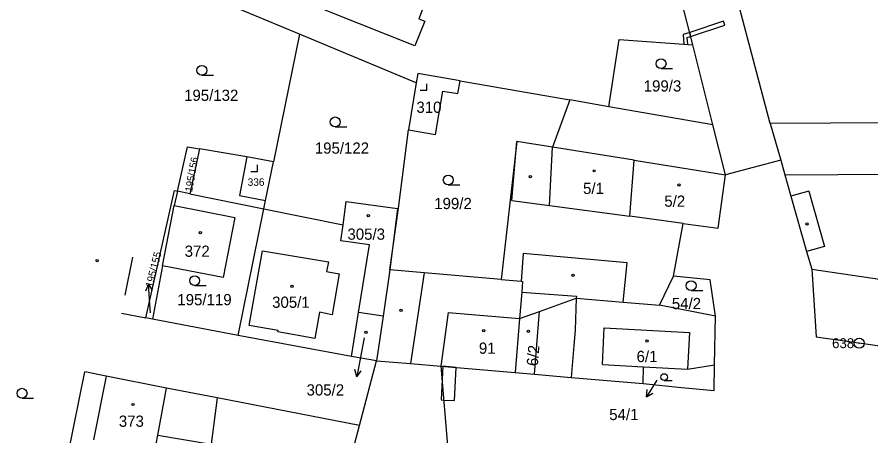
# Model space of a CAD drawing. Extents: x -783948 to -781889, y -1005870 to -1004430.
# Drawn here: x -782682.1 to -782552.8, y -1005413.9 to -1005350.5 of the extents above; entities that cross this region are included whole.
import ezdxf

# ---------------------------------------------------------------- set-up
doc = ezdxf.new("R2010")
doc.units = 0
for name, color, linetype in [('Vrstva 1', 7, 'Continuous'), ('Vrstva 13', 7, 'Continuous'), ('Vrstva 2', 7, 'Continuous'), ('Vrstva 3', 7, 'Continuous'), ('Vrstva 4', 7, 'Continuous'), ('Vrstva 5', 7, 'Continuous'), ('Vrstva 7', 7, 'Continuous'), ('Vrstva 8', 7, 'Continuous')]:
    doc.layers.add(name, color=color, linetype=linetype)

msp = doc.modelspace()

# ---------------------------------------------------------------- linework, layer by layer
at = {"layer": 'Vrstva 1'}
for p, q in [((-782568.05, -1005366.58), (-782581, -1005317.76)), ((-782639.31, -1005353.05), (-782666.74, -1005341.61)), ((-782579.79, -1005354.68), (-782581.54, -1005347.72)), ((-782639.31, -1005353.05), (-782643.26, -1005372.41)), ((-782621.64, -1005360.42), (-782639.31, -1005353.05)), ((-782576.74, -1005366.8), (-782579.79, -1005354.68)), ((-782621.64, -1005360.42), (-782622.85, -1005367.56)), ((-782614.99, -1005360.1), (-782598.41, -1005363.01)), ((-782598.41, -1005363.01), (-782601.05, -1005370.17)), ((-782592.52, -1005364.04), (-782598.41, -1005363.01)), ((-782576.74, -1005366.8), (-782592.52, -1005364.04)), ((-782518.53, -1005366.29), (-782568.05, -1005366.58)), ((-782574.83, -1005374.36), (-782576.74, -1005366.8)), ((-782568.05, -1005366.58), (-782566.48, -1005372.13)), ((-782654.49, -1005370.43), (-782655.91, -1005377.23)), ((-782566.48, -1005372.13), (-782574.83, -1005374.36)), ((-782662.57, -1005396.04), (-782658.25, -1005376.76)), ((-782658.25, -1005376.76), (-782657.8, -1005376.85)), ((-782657.8, -1005376.85), (-782658.29, -1005379.02)), ((-782655.91, -1005377.23), (-782657.8, -1005376.85)), ((-782655.91, -1005377.23), (-782644.71, -1005379.51)), ((-782660.09, -1005388.15), (-782658.29, -1005379.02)), ((-782632.73, -1005381.92), (-782632.25, -1005378.4)), ((-782632.25, -1005378.4), (-782624.5, -1005379.47)), ((-782648.63, -1005398.73), (-782644.71, -1005379.51)), ((-782644.71, -1005379.51), (-782632.73, -1005381.92)), ((-782624.5, -1005379.47), (-782625.63, -1005388.78)), ((-782633.07, -1005384.36), (-782632.73, -1005381.92)), ((-782582.71, -1005389.7), (-782581.23, -1005381.73)), ((-782660.09, -1005388.15), (-782661.6, -1005396.23)), ((-782625.63, -1005388.78), (-782626.66, -1005395.78)), ((-782584.84, -1005394.13), (-782582.71, -1005389.7)), ((-782576.37, -1005395.77), (-782584.84, -1005394.13)), ((-782666.25, -1005395.33), (-782662.57, -1005396.04)), ((-782661.6, -1005396.23), (-782662.57, -1005396.04)), ((-782631.45, -1005401.89), (-782630.38, -1005395.22)), ((-782626.66, -1005395.78), (-782630.38, -1005395.22)), ((-782626.66, -1005395.78), (-782627.67, -1005402.56)), ((-782606.01, -1005396.14), (-782606.67, -1005404.33)), ((-782576.48, -1005403.18), (-782576.37, -1005395.77)), ((-782648.63, -1005398.73), (-782661.6, -1005396.23)), ((-782631.45, -1005401.89), (-782648.63, -1005398.73)), ((-782627.67, -1005402.56), (-782631.45, -1005401.89)), ((-782630.22, -1005412.33), (-782627.67, -1005402.56)), ((-782617.91, -1005403.36), (-782616.88, -1005415.97)), ((-782617.91, -1005403.36), (-782606.67, -1005404.33)), ((-782674.64, -1005418.12), (-782671.83, -1005404.23)), ((-782668.6, -1005404.87), (-782671.83, -1005404.23)), ((-782668.6, -1005404.87), (-782670.5, -1005414.54)), ((-782598.18, -1005405.1), (-782587.31, -1005406.01)), ((-782587.31, -1005406.01), (-782581.49, -1005406.58)), ((-782651.78, -1005408.15), (-782652.71, -1005415.17)), ((-782630.22, -1005412.33), (-782651.78, -1005408.15)), ((-782637.85, -1005441.21), (-782630.22, -1005412.33))]:
    msp.add_line(p, q, dxfattribs=at)
for points in [[(-782635.77, -1005342.28), (-782632.66, -1005334.3), (-782632.25, -1005333.25), (-782630.42, -1005333.92), (-782615.9, -1005339.75), (-782612.83, -1005340.97), (-782613.21, -1005341.94), (-782615.78, -1005348.52), (-782619.8, -1005346.96), (-782621.28, -1005350.7), (-782620.33, -1005351.08), (-782621.85, -1005354.83), (-782634.45, -1005349.81), (-782638.09, -1005348.34), (-782635.77, -1005342.28)], [(-782592.52, -1005364.04), (-782590.91, -1005353.87), (-782579.79, -1005354.68)], [(-782614.99, -1005360.1), (-782621.4, -1005359), (-782621.64, -1005360.42)], [(-782622.85, -1005367.56), (-782618.76, -1005368.27), (-782617.61, -1005361.67), (-782615.34, -1005362.06), (-782614.99, -1005360.1)], [(-782625.63, -1005388.78), (-782624.32, -1005379.44), (-782622.85, -1005367.56)], [(-782657.8, -1005376.85), (-782656.28, -1005370.1), (-782654.49, -1005370.43)], [(-782601.05, -1005370.17), (-782606.45, -1005369.31), (-782608.79, -1005390.24)], [(-782581.23, -1005381.73), (-782589.31, -1005380.65), (-782588.65, -1005372.15), (-782601.05, -1005370.17)], [(-782643.26, -1005372.41), (-782647.3, -1005371.65), (-782654.49, -1005370.43)], [(-782644.71, -1005379.51), (-782644.45, -1005378.24), (-782643.26, -1005372.41)], [(-782566.48, -1005372.13), (-782565.86, -1005374.34), (-782564.92, -1005377.62), (-782562.55, -1005386), (-782561.79, -1005388.68), (-782561.13, -1005398.91), (-782523.94, -1005404.17), (-782523.08, -1005404.21)], [(-782581.23, -1005381.73), (-782575.93, -1005382.44), (-782574.83, -1005374.36)], [(-782658.29, -1005379.02), (-782649.14, -1005380.85), (-782650.89, -1005389.92), (-782660.09, -1005388.15)], [(-782630.38, -1005395.22), (-782628.75, -1005384.97), (-782633.07, -1005384.36)], [(-782608.79, -1005390.24), (-782620.45, -1005389.23), (-782625.63, -1005388.78)], [(-782608.79, -1005390.24), (-782605.78, -1005390.5), (-782605.56, -1005390.52), (-782605.69, -1005392.13), (-782606.01, -1005396.14)], [(-782576.37, -1005395.77), (-782577.18, -1005390.3), (-782582.71, -1005389.7)], [(-782606.01, -1005396.14), (-782603.01, -1005395.06), (-782597.43, -1005393.06)], [(-782597.43, -1005393.06), (-782597.6, -1005397.88), (-782597.79, -1005400.25), (-782598.18, -1005405.1)], [(-782597.43, -1005393.06), (-782590.35, -1005393.67), (-782584.84, -1005394.13)], [(-782627.67, -1005402.56), (-782622.5, -1005402.96), (-782617.91, -1005403.36)], [(-782587.31, -1005406.01), (-782587.25, -1005403.46), (-782580.59, -1005403.81), (-782576.48, -1005403.18)], [(-782581.49, -1005406.58), (-782576.57, -1005407.06), (-782576.48, -1005403.18)], [(-782651.78, -1005408.15), (-782659.44, -1005406.67), (-782668.6, -1005404.87)], [(-782606.67, -1005404.33), (-782603.77, -1005404.58), (-782598.18, -1005405.1)], [(-782661.28, -1005416.42), (-782660.79, -1005413.84), (-782652.71, -1005415.17)]]:
    msp.add_lwpolyline(points, dxfattribs=at)
at = {"layer": 'Vrstva 13'}
for points in [[(-782580.11, -1005353.4), (-782574.96, -1005351.67), (-782575.15, -1005351.1), (-782580.26, -1005352.82)], [(-782581.26, -1005353.1), (-782581.14, -1005354.58), (-782580.53, -1005354.63), (-782580.62, -1005353.54), (-782580.11, -1005353.4), (-782580.26, -1005352.82)], [(-782615.62, -1005403.56), (-782617.65, -1005403.38), (-782617.75, -1005405.36), (-782617.9, -1005408.47), (-782617.49, -1005408.49), (-782615.86, -1005408.57)]]:
    msp.add_lwpolyline(points, close=True, dxfattribs=at)
at = {"layer": 'Vrstva 3'}
for p, q in [((-782584.59, -1005358.27), (-782582.84, -1005358.27)), ((-782654.11, -1005359.28), (-782652.36, -1005359.28)), ((-782620.06, -1005361.55), (-782620.06, -1005360.55)), ((-782621.06, -1005361.55), (-782620.06, -1005361.55)), ((-782633.92, -1005367.1), (-782632.17, -1005367.1)), ((-782645.67, -1005373.84), (-782645.67, -1005372.84)), ((-782646.67, -1005373.84), (-782645.67, -1005373.84)), ((-782616.81, -1005375.9), (-782615.06, -1005375.9)), ((-782655.2, -1005391.15), (-782653.45, -1005391.15)), ((-782580.04, -1005391.91), (-782578.29, -1005391.91)), ((-782584.1, -1005405.51), (-782582.93, -1005405.51)), ((-782681.33, -1005408.22), (-782679.58, -1005408.22))]:
    msp.add_line(p, q, dxfattribs=at)
for centre, radius in [((-782584.59, -1005357.52), 0.75), ((-782654.11, -1005358.53), 0.75), ((-782633.92, -1005366.35), 0.75), ((-782616.81, -1005375.15), 0.75), ((-782655.2, -1005390.4), 0.75), ((-782580.04, -1005391.16), 0.75), ((-782584.11, -1005405.01), 0.502), ((-782681.33, -1005407.47), 0.75)]:
    msp.add_circle(centre, radius, dxfattribs=at)
at = {"layer": 'Vrstva 4'}
for p, q in [((-782607.16, -1005378.27), (-782606.45, -1005369.31)), ((-782601.5, -1005379.02), (-782601.05, -1005370.17)), ((-782647.3, -1005371.65), (-782648.43, -1005377.48)), ((-782588.65, -1005372.15), (-782574.83, -1005374.36)), ((-782565.86, -1005374.34), (-782518.77, -1005374.13)), ((-782648.43, -1005377.48), (-782644.45, -1005378.24)), ((-782562.24, -1005376.86), (-782564.92, -1005377.62)), ((-782562.24, -1005376.86), (-782559.85, -1005385.23)), ((-782607.16, -1005378.27), (-782601.5, -1005379.02)), ((-782601.5, -1005379.02), (-782589.31, -1005380.65)), ((-782559.85, -1005385.23), (-782562.55, -1005386)), ((-782665.71, -1005392.62), (-782664.55, -1005386.84)), ((-782645.73, -1005390.4), (-782644.95, -1005385.88)), ((-782644.95, -1005385.88), (-782634.95, -1005387.53)), ((-782605.46, -1005386.3), (-782605.78, -1005390.5)), ((-782589.7, -1005387.7), (-782605.46, -1005386.3)), ((-782634.95, -1005387.53), (-782635.22, -1005389.02)), ((-782590.35, -1005393.67), (-782589.7, -1005387.7)), ((-782635.22, -1005389.02), (-782633.3, -1005389.35)), ((-782633.3, -1005389.35), (-782634.37, -1005395.56)), ((-782620.45, -1005389.23), (-782622.5, -1005402.96)), ((-782561.79, -1005388.68), (-782541.32, -1005391.69)), ((-782646.97, -1005397.18), (-782645.73, -1005390.4)), ((-782605.69, -1005392.13), (-782597.41, -1005392.76)), ((-782597.41, -1005392.76), (-782597.43, -1005393.06)), ((-782636.3, -1005395.17), (-782637.03, -1005399.16)), ((-782634.37, -1005395.56), (-782636.3, -1005395.17)), ((-782616.83, -1005395.21), (-782617.91, -1005403.36)), ((-782616.83, -1005395.21), (-782606.01, -1005396.14)), ((-782603.77, -1005404.58), (-782603.06, -1005395.68)), ((-782603.06, -1005395.68), (-782603.01, -1005395.06)), ((-782642.57, -1005397.97), (-782646.97, -1005397.18)), ((-782642.61, -1005398.16), (-782642.57, -1005397.97)), ((-782637.03, -1005399.16), (-782642.61, -1005398.16)), ((-782593.48, -1005403.13), (-782587.25, -1005403.46)), ((-782660.79, -1005413.84), (-782659.44, -1005406.67))]:
    msp.add_line(p, q, dxfattribs=at)
msp.add_lwpolyline([(-782593.48, -1005403.13), (-782593.19, -1005397.57), (-782580.3, -1005398.25), (-782580.59, -1005403.81)], dxfattribs=at)
at = {"layer": 'Vrstva 5'}
for centre in [(-782594.72, -1005373.76), (-782604.39, -1005374.63), (-782581.88, -1005375.9), (-782628.92, -1005380.55), (-782562.52, -1005381.81), (-782654.34, -1005383.11), (-782669.96, -1005387.39), (-782597.91, -1005389.58), (-782640.44, -1005391.24), (-782623.95, -1005394.9), (-782629.24, -1005398.24), (-782611.44, -1005397.99), (-782604.68, -1005398.06), (-782586.7, -1005399.56), (-782664.52, -1005409.17)]:
    msp.add_circle(centre, 0.175, dxfattribs=at)
at = {"layer": 'Vrstva 7'}
for p, q in [((-782662.19, -1005390.95), (-782662.62, -1005391.98)), ((-782661.98, -1005393.94), (-782662.19, -1005390.95)), ((-782662.19, -1005390.95), (-782661.62, -1005391.91)), ((-782661.89, -1005395.27), (-782661.98, -1005393.94)), ((-782629.52, -1005399.05), (-782630.09, -1005402.01)), ((-782630.09, -1005402.01), (-782630.66, -1005404.96)), ((-782630.66, -1005404.96), (-782630.96, -1005403.88)), ((-782630.66, -1005404.96), (-782629.98, -1005404.07)), ((-782585.23, -1005405.46), (-782586.78, -1005408.03)), ((-782586.78, -1005408.03), (-782586.69, -1005406.92)), ((-782586.78, -1005408.03), (-782585.83, -1005407.43))]:
    msp.add_line(p, q, dxfattribs=at)
at = {"layer": 'Vrstva 8'}
for radius in [0.75, 0.03]:
    msp.add_circle((-782554.6, -1005399.88), radius, dxfattribs=at)

# ---------------------------------------------------------------- texts
at = {"layer": 'Vrstva 2'}
for s, height, p in [('199/3', 1.7, (-782587.22, -1005361.74)), ('195/132', 1.7, (-782656.8, -1005363.16)), ('310', 1.7, (-782621.63, -1005364.97)), ('195/122', 1.7, (-782637.01, -1005371.16)), ('336', 1.14, (-782647.17, -1005376.03)), ('5/1', 1.7, (-782596.4, -1005377.27)), ('199/2', 1.7, (-782618.93, -1005379.56)), ('5/2', 1.7, (-782584.1, -1005379.2)), ('305/3', 1.7, (-782632.07, -1005384.2)), ('372', 1.7, (-782656.71, -1005386.79)), ('195/119', 1.7, (-782657.82, -1005394.13)), ('305/1', 1.7, (-782643.47, -1005394.52)), ('54/2', 1.7, (-782582.96, -1005394.72)), ('91', 1.7, (-782612.17, -1005401.48)), ('6/1', 1.7, (-782588.3, -1005402.74)), ('305/2', 1.7, (-782638.26, -1005407.81)), ('54/1', 1.7, (-782592.44, -1005411.53)), ('373', 1.7, (-782666.68, -1005412.55))]:
    msp.add_text(s, height=height, dxfattribs=at).set_placement(p)
for s, height, rotation, p in [('195/156', 1.1, 80, (-782655.59, -1005377.02)), ('195/155', 1.139, 76, (-782661.55, -1005391.52)), ('6/2', 1.7, 85, (-782603.26, -1005403.4))]:
    msp.add_text(s, height=height, rotation=rotation, dxfattribs=at).set_placement(p)
at = {"layer": 'Vrstva 8'}
msp.add_text('638', height=1.5, dxfattribs=at).set_placement((-782558.7, -1005400.63))

doc.saveas('drawing.dxf')
